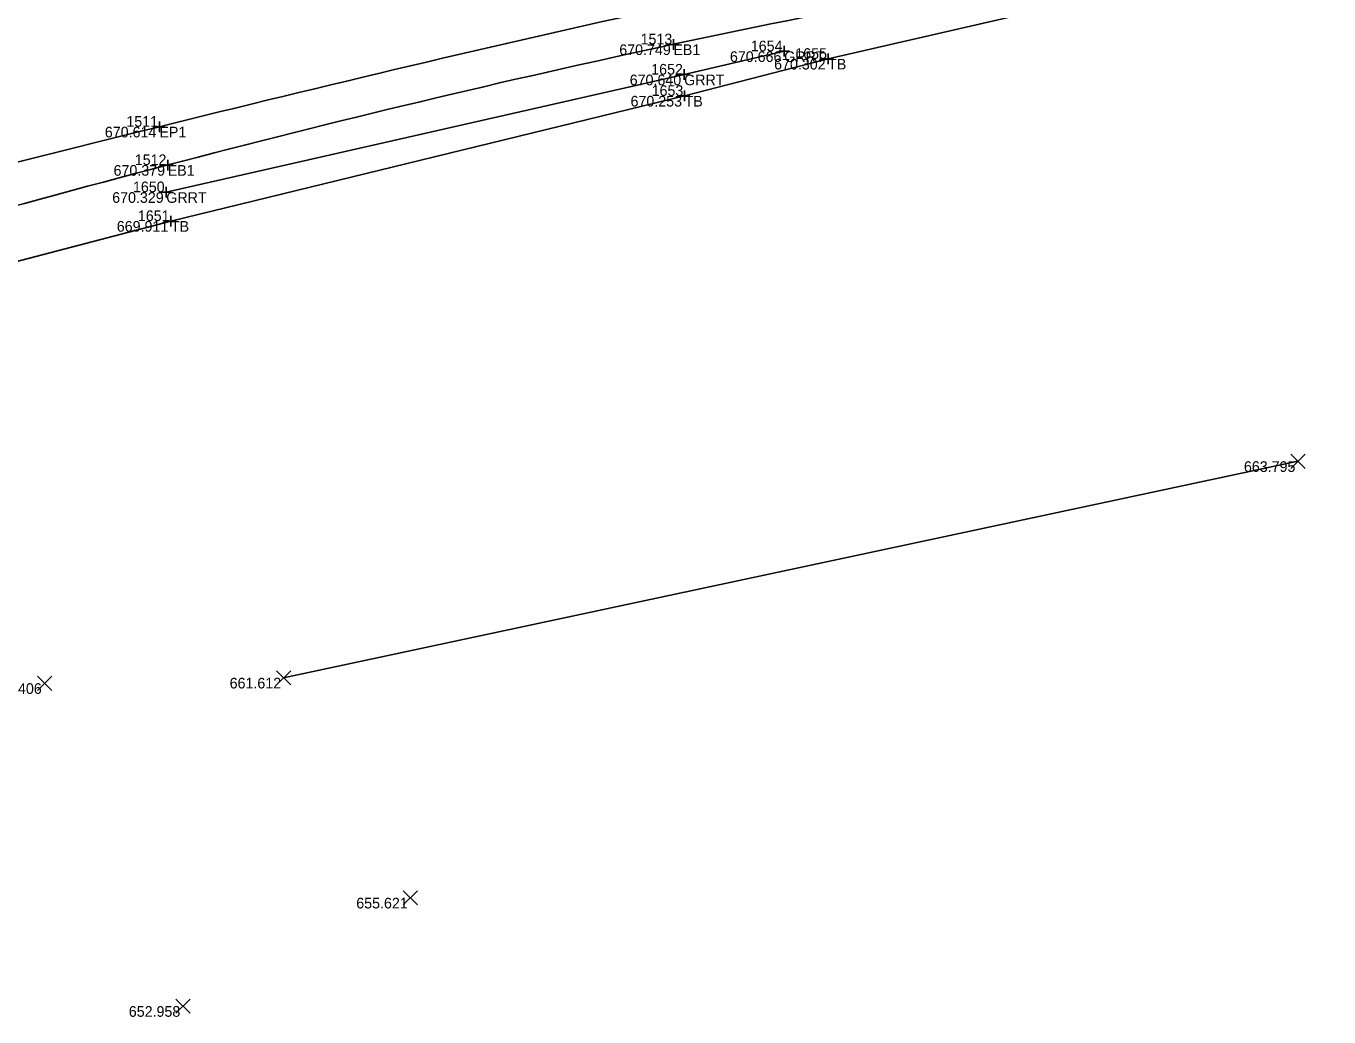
# Model space of a CAD drawing. Extents: x 2197382 to 2204062, y 634117 to 636522.
# Drawn here: x 2203155.5 to 2203277.9, y 635381 to 635474.1 of the extents above; entities that cross this region are included whole.
import ezdxf

# ---------------------------------------------------------------- set-up
doc = ezdxf.new("R2010")
doc.units = 0
for name, color, linetype in [('_CIVIL_CONSTRUCTION', 7, 'Continuous'), ('Default', 7, 'Continuous'), ('GE_P_Alignment_100_Distances', 7, 'Continuous'), ('GE_X_Alignment', 7, 'Continuous'), ('PF_P_Grade_Line', 7, 'Continuous'), ('RD_X_GR_Rt', 7, 'Continuous'), ('RW_X_CL_100_Curve_Data', 7, 'Continuous'), ('SH_Border', 7, 'Continuous'), ('SH_Cut_Line', 7, 'Continuous'), ('SH_Data', 7, 'Continuous')]:
    doc.layers.add(name, color=color, linetype=linetype)

msp = doc.modelspace()

# ---------------------------------------------------------------- linework, layer by layer
at = {"layer": '_CIVIL_CONSTRUCTION'}
for p, q in [((2203215.81, 635472.4), (2203216.81, 635472.4)), ((2203216.31, 635472.9), (2203216.31, 635471.9)), ((2203216.31, 635472.4), (2203216.31, 635472.4)), ((2203226.22, 635471.75), (2203227.22, 635471.75)), ((2203226.72, 635472.25), (2203226.72, 635471.25)), ((2203226.72, 635471.75), (2203226.72, 635471.75)), ((2203230.84, 635471.54), (2203230.84, 635470.54)), ((2203217.32, 635470.06), (2203217.32, 635469.06)), ((2203230.34, 635471.04), (2203231.34, 635471.04)), ((2203230.84, 635471.04), (2203230.84, 635471.04)), ((2203216.82, 635469.56), (2203217.82, 635469.56)), ((2203217.32, 635469.56), (2203217.32, 635469.56)), ((2203216.86, 635467.56), (2203217.86, 635467.56)), ((2203217.36, 635468.06), (2203217.36, 635467.06)), ((2203217.36, 635467.56), (2203217.36, 635467.56)), ((2203168.04, 635465.16), (2203168.04, 635464.16)), ((2203167.54, 635464.66), (2203168.54, 635464.66)), ((2203168.04, 635464.66), (2203168.04, 635464.66)), ((2203168.82, 635461.56), (2203168.82, 635460.56)), ((2203168.32, 635461.06), (2203169.32, 635461.06)), ((2203168.82, 635461.06), (2203168.82, 635461.06)), ((2203168.69, 635459.01), (2203168.69, 635458.01)), ((2203168.19, 635458.51), (2203169.19, 635458.51)), ((2203168.69, 635458.51), (2203168.69, 635458.51)), ((2203168.62, 635455.8), (2203169.62, 635455.8)), ((2203169.12, 635456.3), (2203169.12, 635455.3)), ((2203169.12, 635455.8), (2203169.12, 635455.8))]:
    msp.add_line(p, q, dxfattribs=at)
at = {"layer": 'Default'}
msp.add_line((2203179.71, 635412.88), (2203274.96, 635433.23), dxfattribs=at)
at = {"layer": 'GE_P_Alignment_100_Distances'}
for points in [[(2203509.32, 635523.64), (2203492.71, 635523.63), (2203459.45, 635522.77), (2203409.62, 635520.27), (2203359.91, 635516.08), (2203310.49, 635509.4), (2203261.11, 635501.99), (2203212.05, 635492.43), (2203163.49, 635480.65), (2203115.29, 635467.72), (2203067.64, 635452.84), (2203020.4, 635437.15), (2202989.52, 635425.13), (2202974.27, 635418.84)], [(2203026.75, 635422.16), (2203041.87, 635427.74), (2203072.98, 635437.38), (2203119.81, 635452.49), (2203167.64, 635464.69), (2203215.6, 635476.19), (2203263.86, 635485.77), (2203312.69, 635493.22), (2203361.79, 635499.12), (2203411.11, 635503.52), (2203460.35, 635505.94), (2203493.14, 635506.79), (2203509.37, 635506.86)]]:
    msp.add_open_spline(points, degree=3, dxfattribs=at)
at = {"layer": 'GE_X_Alignment'}
for points in [[(2203509.05, 635533.64), (2203492.46, 635533.63), (2203459.12, 635532.73), (2203409.1, 635530.45), (2203358.98, 635525.69), (2203309.16, 635519.46), (2203259.64, 635511.38), (2203210.26, 635501.87), (2203160.94, 635490.69), (2203112.43, 635476.96), (2203063.47, 635464.85), (2203018.46, 635445.24), (2202987.96, 635434.05), (2202973.99, 635427.15)], [(2203012.65, 635413.01), (2203017.91, 635415.43), (2203039, 635420.9), (2203074.31, 635435.09), (2203121.35, 635447.89), (2203168.65, 635461.38), (2203216.37, 635472.84), (2203264.58, 635481.88), (2203313.28, 635489.5), (2203362.17, 635495.91), (2203411.48, 635500.02), (2203460.32, 635502.3), (2203492.76, 635503.65), (2203508.72, 635503.64)]]:
    msp.add_open_spline(points, degree=3, dxfattribs=at)
at = {"layer": 'PF_P_Grade_Line'}
msp.add_lwpolyline([(2203043.47, 635419.84), (2203073.57, 635429.53), (2203121.13, 635443.22), (2203169.12, 635455.8), (2203217.36, 635467.56), (2203230.84, 635471.04), (2203265.33, 635478.99), (2203314.75, 635483.37), (2203364.47, 635491.57), (2203411.45, 635493.02), (2203461.51, 635493.07), (2203507.42, 635496.53), (2203559.6, 635497.11), (2203609.33, 635499.7), (2203659.06, 635500.52), (2203709.25, 635500.73), (2203757.56, 635500.46), (2203810.24, 635498.93), (2203858.69, 635500.09), (2203907.88, 635499.67), (2203958.73, 635497.99), (2204007.22, 635491.87), (2204054.41, 635491.83)], dxfattribs=at)
at = {"layer": 'RD_X_GR_Rt'}
for p, q in [((2203217.32, 635469.56), (2203226.72, 635471.75)), ((2203168.69, 635458.51), (2203217.32, 635469.56))]:
    msp.add_line(p, q, dxfattribs=at)
at = {"layer": 'RW_X_CL_100_Curve_Data'}
for p, q in [((2203274.3, 635432.56), (2203275.63, 635433.9)), ((2203274.3, 635433.9), (2203275.63, 635432.56)), ((2203156.6, 635411.7), (2203157.93, 635413.04)), ((2203156.6, 635413.04), (2203157.93, 635411.7)), ((2203179.04, 635412.21), (2203180.38, 635413.55)), ((2203179.04, 635413.55), (2203180.38, 635412.21)), ((2203190.94, 635391.54), (2203192.27, 635392.88)), ((2203190.94, 635392.88), (2203192.27, 635391.54)), ((2203169.6, 635381.36), (2203170.93, 635382.7)), ((2203169.6, 635382.7), (2203170.93, 635381.36))]:
    msp.add_line(p, q, dxfattribs=at)

# ---------------------------------------------------------------- texts
at = {"layer": 'SH_Border'}
for s, p in [('EB1', (2203216.31, 635471.4)), ('GRRT', (2203226.72, 635470.75)), ('TB', (2203230.84, 635470.04)), ('GRRT', (2203217.32, 635468.56)), ('TB', (2203217.36, 635466.56)), ('EP1', (2203168.04, 635463.66)), ('EB1', (2203168.82, 635460.06)), ('GRRT', (2203168.69, 635457.51)), ('TB', (2203169.12, 635454.8))]:
    msp.add_text(s, height=1, dxfattribs=at).set_placement(p)
at = {"layer": 'SH_Cut_Line'}
for s, p in [('1513', (2203213.23, 635472.4)), ('1654', (2203223.58, 635471.75)), ('1655', (2203227.76, 635471.04)), ('1652', (2203214.23, 635469.56)), ('1653', (2203214.27, 635467.56)), ('1511', (2203164.94, 635464.66)), ('1512', (2203165.73, 635461.06)), ('1650', (2203165.56, 635458.51)), ('1651', (2203166.02, 635455.8))]:
    msp.add_text(s, height=1, dxfattribs=at).set_placement(p)
at = {"layer": 'SH_Data'}
for s, p in [('670.749', (2203211.23, 635471.4)), ('670.666', (2203221.62, 635470.75)), ('670.302', (2203225.77, 635470.04)), ('670.640', (2203212.21, 635468.56)), ('670.253', (2203212.29, 635466.56)), ('670.614', (2203162.92, 635463.66)), ('670.379', (2203163.74, 635460.06)), ('670.329', (2203163.61, 635457.51)), ('669.911', (2203164.04, 635454.8)), ('663.795', (2203269.89, 635432.23)), ('661.406', (2203152.16, 635411.37)), ('661.612', (2203174.64, 635411.88)), ('655.621', (2203186.53, 635391.21)), ('652.958', (2203165.17, 635381.03))]:
    msp.add_text(s, height=1, dxfattribs=at).set_placement(p)

doc.saveas('drawing.dxf')
